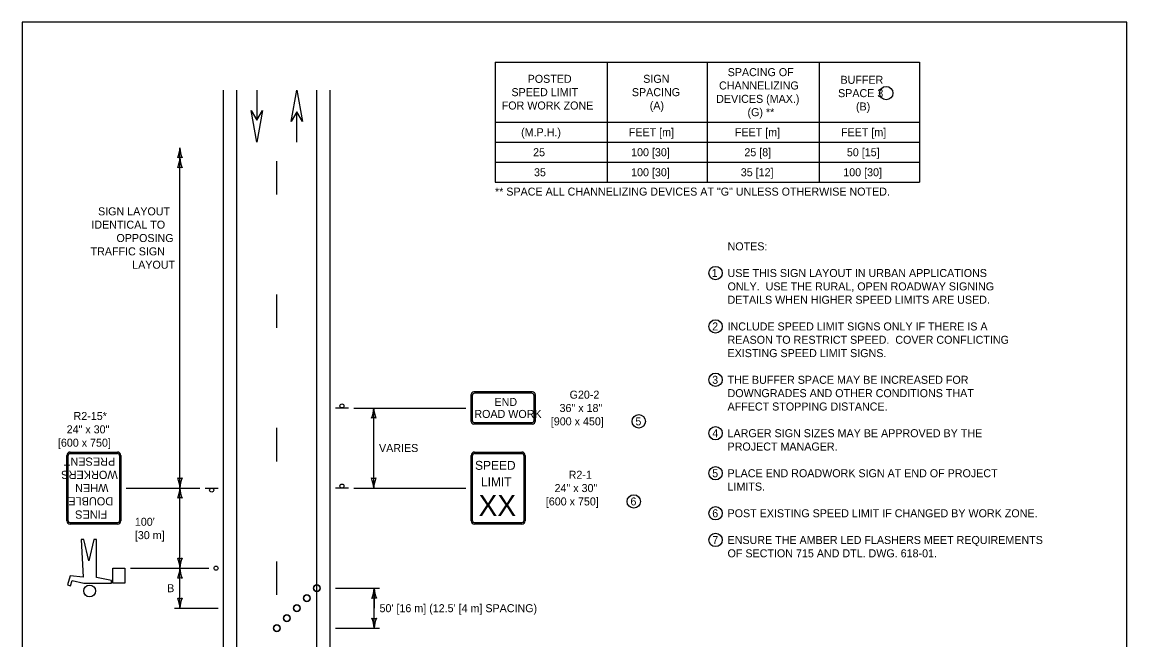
# Model space of a CAD drawing. Extents: x 49991.4 to 50021, y 49987.6 to 50011.4.
# Drawn here: x 50000.34 to 50008.61, y 50006.63 to 50011.26 of the extents above; entities that cross this region are included whole.
import ezdxf

# ---------------------------------------------------------------- set-up
doc = ezdxf.new("R2010")
doc.units = 0
for name, color, linetype in [('Level 1', 7, 'Continuous'), ('Level 2', 7, 'Continuous'), ('Level 3', 7, 'Continuous')]:
    doc.layers.add(name, color=color, linetype=linetype)

msp = doc.modelspace()

# ---------------------------------------------------------------- linework, layer by layer
at = {"layer": 'Level 1'}
for p, q in [((50001.8443, 50000.5714), (50001.8443, 50010.7538)), ((50001.9443, 50000.5714), (50001.9443, 50010.7538)), ((50002.0942, 50010.7538), (50002.0942, 50010.5279)), ((50002.0945, 50010.7538), (50002.0945, 50010.5279)), ((50002.5443, 50006.5714), (50002.5443, 50010.7538)), ((50002.6443, 50000.5714), (50002.6443, 50010.7538)), ((50002.3939, 50010.3637), (50002.3939, 50010.5896)), ((50002.3942, 50010.3637), (50002.3942, 50010.5896)), ((50002.2443, 50009.9716), (50002.2443, 50010.2216)), ((50002.2443, 50008.9716), (50002.2443, 50009.2216)), ((50004.1607, 50008.4914), (50003.7207, 50008.4914)), ((50004.1607, 50008.4914), (50003.7207, 50008.4914)), ((50004.1557, 50008.4814), (50003.7257, 50008.4814)), ((50004.1557, 50008.4814), (50003.7257, 50008.4814)), ((50003.7007, 50008.2714), (50003.7007, 50008.4714)), ((50003.7007, 50008.2714), (50003.7007, 50008.4714)), ((50003.7107, 50008.2764), (50003.7107, 50008.4664)), ((50003.7107, 50008.2764), (50003.7107, 50008.4664)), ((50004.1707, 50008.4664), (50004.1707, 50008.2764)), ((50004.1707, 50008.4664), (50004.1707, 50008.2764)), ((50004.1807, 50008.4714), (50004.1807, 50008.2714)), ((50004.1807, 50008.4714), (50004.1807, 50008.2714)), ((50002.7803, 50008.3714), (50002.6843, 50008.3714)), ((50004.1607, 50008.2513), (50003.7207, 50008.2513)), ((50004.1607, 50008.2513), (50003.7207, 50008.2513)), ((50004.1557, 50008.2614), (50003.7257, 50008.2614)), ((50004.1557, 50008.2614), (50003.7257, 50008.2614)), ((50002.2443, 50007.9716), (50002.2443, 50008.2216)), ((50000.671, 50007.5266), (50000.671, 50008.0161)), ((50000.6815, 50007.5266), (50000.6815, 50008.0161)), ((50000.6963, 50008.0414), (50001.0507, 50008.0414)), ((50000.6963, 50008.0309), (50001.0507, 50008.0309)), ((50001.0655, 50008.0161), (50001.0655, 50007.5266)), ((50001.076, 50008.0161), (50001.076, 50007.5266)), ((50003.7007, 50007.5266), (50003.7007, 50008.0161)), ((50003.7112, 50007.5266), (50003.7112, 50008.0161)), ((50003.726, 50008.0414), (50004.0804, 50008.0414)), ((50003.726, 50008.0309), (50004.0804, 50008.0309)), ((50003.9032, 50008.0414), (50003.9032, 50008.0414)), ((50004.0952, 50008.0161), (50004.0952, 50007.5266)), ((50004.1058, 50008.0161), (50004.1058, 50007.5266)), ((50001.7083, 50007.7714), (50001.8043, 50007.7714)), ((50002.7803, 50007.7714), (50002.6843, 50007.7714)), ((50002.7803, 50007.7714), (50002.6843, 50007.7714)), ((50001.0507, 50007.5119), (50000.6963, 50007.5119)), ((50001.0507, 50007.5013), (50000.6963, 50007.5013)), ((50000.8735, 50007.5013), (50000.8735, 50007.5013)), ((50004.0804, 50007.5119), (50003.726, 50007.5119)), ((50004.0804, 50007.5013), (50003.726, 50007.5013)), ((50000.7972, 50007.3867), (50000.7789, 50007.3867)), ((50000.7789, 50007.3867), (50000.7937, 50007.1033)), ((50000.8355, 50007.2254), (50000.7972, 50007.3867)), ((50000.8738, 50007.3867), (50000.8355, 50007.2254)), ((50000.892, 50007.3867), (50000.8738, 50007.3867)), ((50000.892, 50007.1004), (50000.892, 50007.3867)), ((50001.0148, 50007.0589), (50001.0148, 50007.1714)), ((50001.0148, 50007.1714), (50001.1067, 50007.1714)), ((50001.1067, 50007.1714), (50001.1067, 50007.0589)), ((50002.2443, 50006.9716), (50002.2443, 50007.2216)), ((50000.6961, 50007.1143), (50000.6761, 50007.0455)), ((50000.7937, 50007.1033), (50000.6961, 50007.1143)), ((50000.6981, 50007.04), (50000.7108, 50007.0796)), ((50000.7108, 50007.0796), (50000.7976, 50007.0596)), ((50001.0045, 50007.0782), (50000.892, 50007.1004)), ((50001.0045, 50007.0596), (50001.0045, 50007.0782)), ((50000.6761, 50007.0455), (50000.6981, 50007.04)), ((50000.7976, 50007.0596), (50001.0045, 50007.0596)), ((50001.1067, 50007.0589), (50001.0148, 50007.0589))]:
    msp.add_line(p, q, dxfattribs=at)
for points in [[(50008.6146, 50011.2628), (50000.3356, 50011.2628), (50000.3356, 50000.0624), (50008.6146, 50000.0624)], [(50002.3522, 50010.5173), (50002.3939, 50010.7538), (50002.4358, 50010.5173), (50002.3939, 50010.5895)], [(50002.1362, 50010.6002), (50002.0945, 50010.3637), (50002.0526, 50010.6002), (50002.0945, 50010.528)]]:
    msp.add_lwpolyline(points, close=True, dxfattribs=at)
for centre, radius in [((50002.7323, 50008.3867), 0.0152), ((50001.7563, 50007.7561), 0.0152), ((50002.7323, 50007.7866), 0.0152), ((50002.7323, 50007.7867), 0.0152), ((50001.7891, 50007.1714), 0.0152), ((50000.8412, 50007.0006), 0.0442), ((50002.5443, 50007.0214), 0.025), ((50002.4693, 50006.9464), 0.025), ((50002.3193, 50006.7964), 0.025), ((50002.3943, 50006.8714), 0.025), ((50002.2443, 50006.7214), 0.025)]:
    msp.add_circle(centre, radius, dxfattribs=at)
for centre, radius, start, end in [((50003.7207, 50008.4714), 0.02, 90, 180), ((50003.7207, 50008.4714), 0.02, 90, 180), ((50003.7257, 50008.4664), 0.015, 90, 180), ((50003.7257, 50008.4664), 0.015, 90, 180), ((50004.1557, 50008.4664), 0.015, 0, 90), ((50004.1557, 50008.4664), 0.015, 0, 90), ((50004.1607, 50008.4714), 0.02, 0, 90), ((50004.1607, 50008.4714), 0.02, 0, 90), ((50003.7206, 50008.2714), 0.02, 180, 270), ((50003.7206, 50008.2714), 0.02, 180, 270), ((50003.7257, 50008.2764), 0.015, 180, 270), ((50003.7257, 50008.2764), 0.015, 180, 270), ((50004.1557, 50008.2764), 0.015, 270, 0), ((50004.1557, 50008.2764), 0.015, 270, 0), ((50004.1606, 50008.2714), 0.02, 270, 0), ((50004.1606, 50008.2714), 0.02, 270, 0), ((50000.6963, 50008.0161), 0.0253, 90, 180), ((50000.6963, 50008.0161), 0.0148, 90, 180), ((50001.0507, 50008.0161), 0.0253, 360, 90), ((50001.0507, 50008.0161), 0.0148, 360, 90), ((50003.726, 50008.0161), 0.0253, 90, 180), ((50003.726, 50008.0161), 0.0148, 90, 180), ((50004.0804, 50008.0161), 0.0253, 0, 90), ((50004.0804, 50008.0161), 0.0148, 0, 90), ((50000.6963, 50007.5266), 0.0253, 180, 270), ((50000.6963, 50007.5266), 0.0148, 180, 270), ((50001.0507, 50007.5266), 0.0148, 270, 360), ((50001.0507, 50007.5266), 0.0253, 270, 360), ((50003.726, 50007.5266), 0.0253, 180, 270), ((50003.726, 50007.5266), 0.0148, 180, 270), ((50004.0804, 50007.5266), 0.0148, 270, 360), ((50004.0804, 50007.5266), 0.0253, 270, 360), ((50002.5443, 50007.0214), 0.025, 0, 180), ((50002.5443, 50007.0214), 0.025, 180, 0), ((50002.4693, 50006.9464), 0.025, 0, 180), ((50002.4693, 50006.9464), 0.025, 180, 0), ((50002.3193, 50006.7964), 0.025, 0, 180), ((50002.3943, 50006.8714), 0.025, 0, 180), ((50002.3943, 50006.8714), 0.025, 180, 0), ((50002.2443, 50006.7214), 0.025, 0, 180), ((50002.3193, 50006.7964), 0.025, 180, 0), ((50002.2443, 50006.7214), 0.025, 180, 0)]:
    msp.add_arc(centre, radius, start, end, dxfattribs=at)
at = {"layer": 'Level 2'}
for p, q in [((50003.8794, 50010.9628), (50003.8794, 50010.0628)), ((50003.8794, 50010.9628), (50005.4694, 50010.9628)), ((50004.7194, 50010.9628), (50004.7194, 50010.0628)), ((50005.4694, 50010.9628), (50005.4694, 50010.0628)), ((50005.4694, 50010.9628), (50007.0594, 50010.9628)), ((50006.3094, 50010.9628), (50006.3094, 50010.0628)), ((50007.0594, 50010.9628), (50007.0594, 50010.0628)), ((50003.8794, 50010.5128), (50005.4694, 50010.5128)), ((50005.4694, 50010.5128), (50007.0594, 50010.5128)), ((50003.8794, 50010.3628), (50005.4694, 50010.3628)), ((50005.4694, 50010.3628), (50007.0594, 50010.3628)), ((50003.8794, 50010.2128), (50005.4694, 50010.2128)), ((50005.4694, 50010.2128), (50007.0594, 50010.2128)), ((50003.8794, 50010.0628), (50005.4694, 50010.0628)), ((50005.4694, 50010.0628), (50007.0594, 50010.0628))]:
    msp.add_line(p, q, dxfattribs=at)
for centre in [(50006.8109, 50010.7305), (50005.5319, 50009.3826), (50005.5319, 50008.9826), (50005.5319, 50008.5826), (50004.9564, 50008.2714), (50005.5319, 50008.1826), (50005.5319, 50007.8826), (50004.919, 50007.6714), (50005.5319, 50007.5826), (50005.5319, 50007.3826)]:
    msp.add_circle(centre, 0.0501, dxfattribs=at)
at = {"layer": 'Level 3'}
for p, q in [((50001.5183, 50007.7714), (50001.5183, 50010.3214)), ((50002.8203, 50008.3714), (50003.6607, 50008.3714)), ((50002.9703, 50007.7714), (50002.9703, 50008.3714)), ((50001.116, 50007.7714), (50001.6683, 50007.7714)), ((50001.5183, 50007.1714), (50001.5183, 50007.7714)), ((50002.8203, 50007.7714), (50003.6607, 50007.7714)), ((50001.1467, 50007.1714), (50001.7338, 50007.1714)), ((50001.5183, 50006.8714), (50001.5183, 50007.1714)), ((50002.6843, 50007.0214), (50003.014, 50007.0214)), ((50002.974, 50006.7214), (50002.974, 50007.0214)), ((50002.974, 50006.9948), (50002.974, 50006.8714)), ((50001.4783, 50006.8714), (50001.8043, 50006.8714)), ((50002.6843, 50006.7214), (50003.014, 50006.7214))]:
    msp.add_line(p, q, dxfattribs=at)
for centre, radius, start, end in [((50001.2962, 50010.3305), 0.2223, 337.45601, 357.63952), ((50001.751, 50010.3329), 0.233, 182.82731, 202.07716), ((50001.5183, 50010.1932), 0.0548, 72.13882, 107.86118), ((50001.2962, 50010.2571), 0.2223, 337.45601, 357.63952), ((50001.751, 50010.2594), 0.233, 182.82731, 202.07716), ((50001.5183, 50010.1197), 0.0548, 72.13882, 107.86118), ((50002.7482, 50008.3805), 0.2223, 337.45601, 357.63952), ((50003.203, 50008.3829), 0.233, 182.82731, 202.07716), ((50002.9703, 50008.2432), 0.0548, 72.13882, 107.86118), ((50001.5183, 50007.8996), 0.0548, 252.13882, 287.86118), ((50001.2856, 50007.7599), 0.233, 2.82731, 22.07716), ((50001.7404, 50007.7622), 0.2223, 157.45601, 177.63952), ((50002.9703, 50007.8996), 0.0548, 252.13882, 287.86118), ((50002.7376, 50007.7599), 0.233, 2.82731, 22.07716), ((50003.1924, 50007.7622), 0.2223, 157.45601, 177.63952), ((50001.2962, 50007.7805), 0.2223, 337.45601, 357.63952), ((50001.751, 50007.7829), 0.233, 182.82731, 202.07716), ((50001.5183, 50007.6432), 0.0548, 72.13882, 107.86118), ((50001.5183, 50007.2996), 0.0548, 252.13882, 287.86118), ((50001.2856, 50007.1599), 0.233, 2.82731, 22.07716), ((50001.7404, 50007.1622), 0.2223, 157.45601, 177.63952), ((50001.2962, 50007.1805), 0.2223, 337.45601, 357.63952), ((50001.751, 50007.1829), 0.233, 182.82731, 202.07716), ((50001.5183, 50007.0432), 0.0548, 72.13882, 107.86118), ((50002.7518, 50007.0305), 0.2223, 337.45601, 357.63952), ((50003.2067, 50007.0329), 0.233, 182.82731, 202.07716), ((50001.5183, 50006.9996), 0.0548, 252.13882, 287.86118), ((50001.2856, 50006.8599), 0.233, 2.82731, 22.07716), ((50001.7404, 50006.8622), 0.2223, 157.45601, 177.63952), ((50002.974, 50006.8932), 0.0548, 72.13882, 107.86118), ((50002.974, 50006.8496), 0.0548, 252.13882, 287.86118), ((50002.7412, 50006.7099), 0.233, 2.82731, 22.07716), ((50003.1961, 50006.7122), 0.2223, 157.45601, 177.63952)]:
    msp.add_arc(centre, radius, start, end, dxfattribs=at)

# ---------------------------------------------------------------- texts
at = {"layer": 'Level 1'}
for s, height, p in [('END', 0.06, (50003.8755, 50008.3869)), ('END', 0.06, (50003.8755, 50008.3869)), ('ROAD WORK', 0.06, (50003.7247, 50008.2969)), ('ROAD WORK', 0.06, (50003.7247, 50008.2969)), ('SPEED', 0.06695, (50003.7301, 50007.9082)), ('LIMIT', 0.06695, (50003.7744, 50007.7844)), ('XX', 0.15772, (50003.7561, 50007.5624))]:
    msp.add_text(s, height=height, dxfattribs=at).set_placement(p)
for s, p in [('PRESENT', (50001.034, 50008.0003)), ('WORKERS', (50001.052, 50007.9011)), ('WHEN', (50000.9826, 50007.802)), ('DOUBLE', (50001.0181, 50007.7028)), ('FINES', (50000.9746, 50007.6037))]:
    msp.add_text(s, height=0.06118, rotation=180, dxfattribs=at).set_placement(p)
at = {"layer": 'Level 2'}
for s, p in [('SPACING OF', (50005.6229, 50010.8578)), ('POSTED', (50004.1241, 50010.8078)), ('SIGN', (50004.99, 50010.8078)), ('CHANNELIZING', (50005.5582, 50010.7578)), ('BUFFER', (50006.4683, 50010.8005)), ('SPEED LIMIT', (50004.0028, 50010.7078)), ('SPACING', (50004.905, 50010.7078)), ('DEVICES (MAX.)', (50005.5367, 50010.6578)), ('SPACE 3', (50006.4503, 50010.7005)), ('FOR WORK ZONE', (50003.9298, 50010.6078)), ('(A)', (50005.039, 50010.6078)), ('(B)', (50006.5843, 50010.6005)), ('(G) **', (50005.7715, 50010.5578)), ('(M.P.H.)', (50004.0749, 50010.4078)), ('FEET [m]', (50004.8821, 50010.4078)), ('FEET [m]', (50005.6771, 50010.4078)), ('FEET [m]', (50006.4721, 50010.4078)), ('25', (50004.1651, 50010.2578)), ('100 [30]', (50004.8993, 50010.2578)), ('25 [8]', (50005.7481, 50010.2578)), ('50 [15]', (50006.5162, 50010.2578)), ('35', (50004.1717, 50010.1078)), ('100 [30]', (50004.8993, 50010.1078)), ('35 [12]', (50005.7212, 50010.1078)), ('100 [30]', (50006.4893, 50010.1078)), ('** SPACE ALL CHANNELIZING DEVICES AT "G" UNLESS OTHERWISE NOTED.', (50003.8794, 50009.9628)), ('SIGN LAYOUT', (50000.9048, 50009.8149)), ('IDENTICAL TO', (50000.8546, 50009.7149)), ('OPPOSING', (50001.0427, 50009.6149)), ('TRAFFIC SIGN', (50000.8487, 50009.5149)), ('NOTES:', (50005.622, 50009.5526)), ('LAYOUT', (50001.1608, 50009.4149)), ('1', (50005.5032, 50009.3527)), ('USE THIS SIGN LAYOUT IN URBAN APPLICATIONS', (50005.622, 50009.3526)), ('ONLY.  USE THE RURAL, OPEN ROADWAY SIGNING', (50005.622, 50009.2526)), ('DETAILS WHEN HIGHER SPEED LIMITS ARE USED.', (50005.622, 50009.1526)), ('2', (50005.5068, 50008.9526)), ('INCLUDE SPEED LIMIT SIGNS ONLY IF THERE IS A', (50005.622, 50008.9526)), ('REASON TO RESTRICT SPEED.  COVER CONFLICTING', (50005.622, 50008.8526)), ('EXISTING SPEED LIMIT SIGNS.', (50005.622, 50008.7526)), ('3', (50005.5067, 50008.5526)), ('THE BUFFER SPACE MAY BE INCREASED FOR', (50005.622, 50008.5526)), ('G20-2', (50004.4384, 50008.4414)), ('DOWNGRADES AND OTHER CONDITIONS THAT', (50005.622, 50008.4526)), ('36" x 18"', (50004.3632, 50008.3414)), ('AFFECT STOPPING DISTANCE.', (50005.622, 50008.3526)), ('R2-15*', (50000.7212, 50008.2814)), ('24" x 30"', (50000.6696, 50008.1814)), ('[900 x 450]', (50004.2976, 50008.2414)), ('5', (50004.9315, 50008.2414)), ('[600 x 750]', (50000.6041, 50008.0814)), ('4', (50005.508, 50008.1526)), ('LARGER SIGN SIZES MAY BE APPROVED BY THE ', (50005.622, 50008.1526)), ('VARIES', (50003.0103, 50008.0414)), ('PROJECT MANAGER.', (50005.622, 50008.0526)), ('R2-1', (50004.4313, 50007.8414)), ('5', (50005.507, 50007.8526)), ('PLACE END ROADWORK SIGN AT END OF PROJECT', (50005.622, 50007.8526)), ('LIMITS.', (50005.622, 50007.7526)), ('24" x 30"', (50004.3257, 50007.7414)), ('[600 x 750]', (50004.2602, 50007.6414)), ('6', (50004.8944, 50007.6414)), ('6', (50005.5074, 50007.5526)), ('POST EXISTING SPEED LIMIT IF CHANGED BY WORK ZONE.', (50005.622, 50007.5526)), ("100'", (50001.1806, 50007.4889)), ('[30 m]', (50001.1806, 50007.3889)), ('7', (50005.5081, 50007.3526)), ('ENSURE THE AMBER LED FLASHERS MEET REQUIREMENTS', (50005.622, 50007.3526)), ('OF SECTION 715 AND DTL. DWG. 618-01.', (50005.622, 50007.2526)), ('B', (50001.4228, 50006.9914)), ("50' [16 m] (12.5' [4 m] SPACING)", (50003.014, 50006.8414))]:
    msp.add_text(s, height=0.06, dxfattribs=at).set_placement(p)

doc.saveas('drawing.dxf')
